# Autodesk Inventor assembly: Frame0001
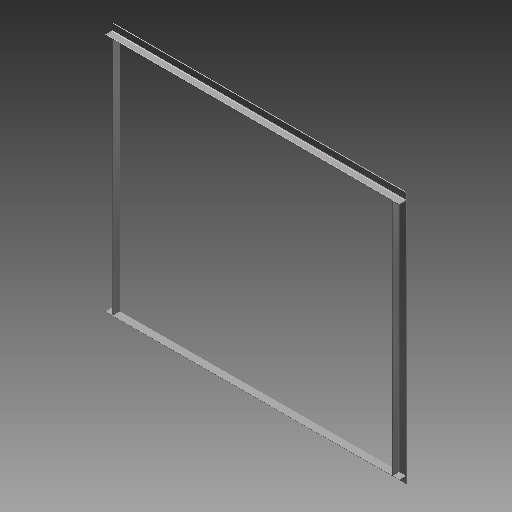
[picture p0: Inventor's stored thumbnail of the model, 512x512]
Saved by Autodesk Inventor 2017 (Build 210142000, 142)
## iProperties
Created: 2020-09
Part Number: Frame0001
Document SubType Name: Assembly
Designer: X
Mass: 40058.5 g
Surface Area: 20492.3 cm^2
Volume: 5102.99 cm^3
Density: 7.85 g/cm^3
_FrameDoc: Frame Assembly
_Version: 15.0.0
Author: X
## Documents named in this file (10)
- C:\Users\WindowsX\Desktop\brama\rama_bramy\Frame\Frame0001.iam
- C:\Users\WindowsX\Desktop\brama\rama_bramy\Frame\Skeleton0001.ipt
- C:\Users\WindowsX\Desktop\brama\rama_bramy\Frame\PN L60x60x5 00000005.ipt
- PN L60x60x5 00000005.ipt
- C:\Users\WindowsX\Desktop\brama\rama_bramy\Frame\PN L60x60x5 00000006.ipt
- PN L60x60x5 00000006.ipt
- C:\Users\WindowsX\Desktop\brama\rama_bramy\Frame\PN L60x60x5 00000007.ipt
- PN L60x60x5 00000007.ipt
- C:\Users\WindowsX\Desktop\brama\rama_bramy\Frame\PN L60x60x5 00000008.ipt
- PN L60x60x5 00000008.ipt
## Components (5 placed, 5 different names)
1. Model odniesienia ramy
2. PN L60x60x5 00000005:1
3. PN L60x60x5 00000006:1
4. PN L60x60x5 00000007:1
5. PN L60x60x5 00000008:1
